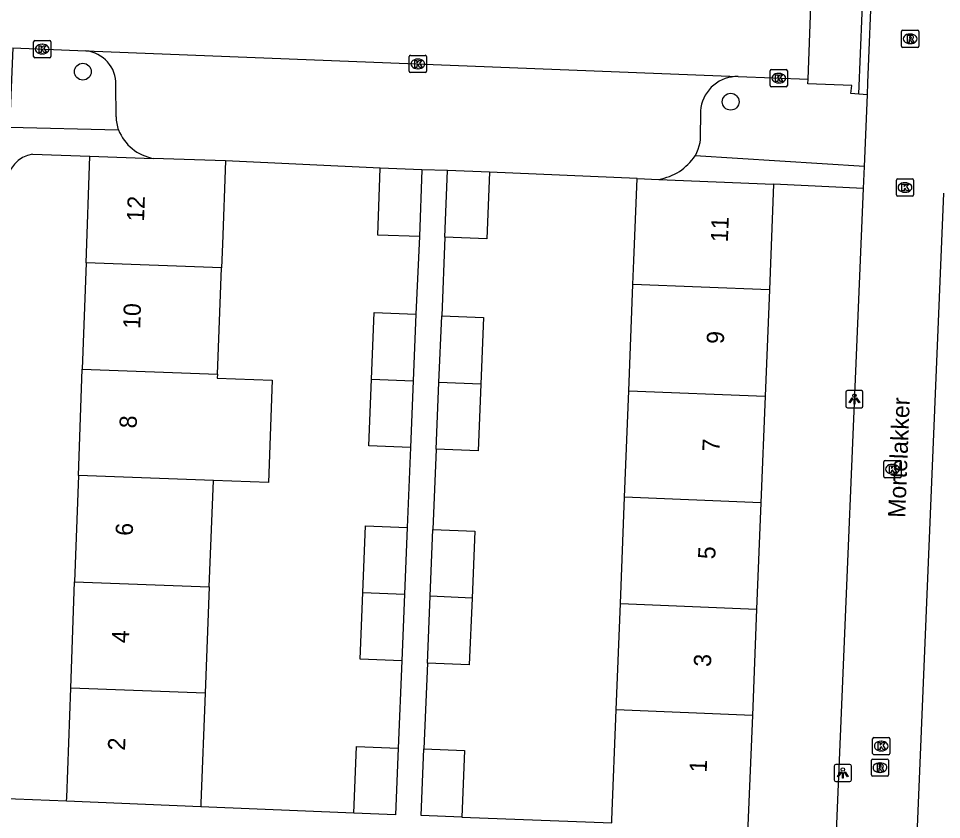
# Model space of a CAD drawing. Extents: x 161355 to 162026, y 386504 to 387459.
# Drawn here: x 161623.1 to 161676.7, y 386682.8 to 386729.4 of the extents above; entities that cross this region are included whole.
import ezdxf

# ---------------------------------------------------------------- set-up
doc = ezdxf.new("R2010")
doc.units = 0
for name, color, linetype in [('IMGEO_Boom', 7, 'Continuous'), ('IMGEO_Kolk', 7, 'Continuous'), ('IMGEO_Lichtpunt', 7, 'Continuous'), ('IMGEO_Openbare_ruimte_label', 7, 'Continuous'), ('IMGEO_Pand', 7, 'Continuous'), ('IMGEO_Pand_nummerreeks', 7, 'Continuous'), ('IMGEO_Parkeervlak_open', 7, 'Continuous'), ('IMGEO_Rijbaan_lokaal_open', 7, 'Continuous'), ('IMGEO_Rioolput', 7, 'Continuous'), ('IMGEO_Voetpad_open', 7, 'Continuous')]:
    doc.layers.add(name, color=color, linetype=linetype)

msp = doc.modelspace()

# ---------------------------------------------------------------- linework, layer by layer
at = {"layer": 'IMGEO_Boom'}
for centre in [(161626.866, 386726.264), (161664.481, 386724.517)]:
    msp.add_circle(centre, 0.489, dxfattribs=at)
at = {"layer": 'IMGEO_Kolk'}
for p, q in [((161624.007, 386727.146), (161624.007, 386727.998)), ((161624.082, 386728.072), (161624.934, 386728.072)), ((161624.495, 386727.852), (161624.52, 386727.852)), ((161625.008, 386727.998), (161625.008, 386727.146)), ((161624.518, 386727.292), (161624.493, 386727.292)), ((161624.934, 386727.072), (161624.082, 386727.072)), ((161645.819, 386726.286), (161645.819, 386727.138)), ((161645.894, 386727.212), (161646.746, 386727.212)), ((161646.307, 386726.992), (161646.332, 386726.992)), ((161646.82, 386727.138), (161646.82, 386726.286)), ((161646.746, 386726.212), (161645.894, 386726.212)), ((161646.33, 386726.432), (161646.305, 386726.432)), ((161666.772, 386725.459), (161666.772, 386726.311)), ((161666.847, 386726.385), (161667.699, 386726.385)), ((161667.773, 386726.311), (161667.773, 386725.459)), ((161667.26, 386726.165), (161667.285, 386726.165)), ((161667.699, 386725.385), (161666.847, 386725.385)), ((161667.283, 386725.605), (161667.258, 386725.605)), ((161674.102, 386719.107), (161674.102, 386719.959)), ((161674.177, 386720.033), (161675.029, 386720.033)), ((161674.59, 386719.813), (161674.615, 386719.813)), ((161675.103, 386719.959), (161675.103, 386719.107)), ((161674.613, 386719.253), (161674.588, 386719.253)), ((161675.029, 386719.033), (161674.177, 386719.033)), ((161673.452, 386703.666), (161674.304, 386703.666)), ((161673.377, 386702.74), (161673.377, 386703.592)), ((161673.865, 386703.446), (161673.89, 386703.446)), ((161674.378, 386703.592), (161674.378, 386702.74)), ((161674.304, 386702.666), (161673.452, 386702.666)), ((161673.888, 386702.886), (161673.863, 386702.886)), ((161672.723, 386686.65), (161672.723, 386687.502)), ((161672.798, 386687.576), (161673.65, 386687.576)), ((161673.211, 386687.356), (161673.236, 386687.356)), ((161673.724, 386687.502), (161673.724, 386686.65)), ((161673.65, 386686.576), (161672.798, 386686.576)), ((161673.234, 386686.796), (161673.209, 386686.796))]:
    msp.add_line(p, q, dxfattribs=at)
for points in [[(161624.007, 386727.146), (161624.007, 386727.998)], [(161624.082, 386728.072), (161624.934, 386728.072)], [(161625.008, 386727.998), (161625.008, 386727.146)], [(161624.328, 386727.772), (161624.451, 386727.772), (161624.451, 386727.621), (161624.581, 386727.772), (161624.745, 386727.772), (161624.599, 386727.621), (161624.752, 386727.372), (161624.6, 386727.372), (161624.515, 386727.536), (161624.451, 386727.469), (161624.451, 386727.372), (161624.328, 386727.372), (161624.328, 386727.772)], [(161624.934, 386727.072), (161624.082, 386727.072)], [(161645.819, 386726.286), (161645.819, 386727.138)], [(161645.894, 386727.212), (161646.746, 386727.212)], [(161646.14, 386726.912), (161646.263, 386726.912), (161646.263, 386726.761), (161646.393, 386726.912), (161646.557, 386726.912), (161646.411, 386726.761), (161646.564, 386726.512), (161646.412, 386726.512), (161646.327, 386726.676), (161646.263, 386726.609), (161646.263, 386726.512), (161646.14, 386726.512), (161646.14, 386726.912)], [(161646.82, 386727.138), (161646.82, 386726.286)], [(161646.746, 386726.212), (161645.894, 386726.212)], [(161666.772, 386725.459), (161666.772, 386726.311)], [(161666.847, 386726.385), (161667.699, 386726.385)], [(161667.773, 386726.311), (161667.773, 386725.459)], [(161667.093, 386726.085), (161667.216, 386726.085), (161667.216, 386725.934), (161667.346, 386726.085), (161667.51, 386726.085), (161667.364, 386725.934), (161667.517, 386725.685), (161667.365, 386725.685), (161667.28, 386725.849), (161667.216, 386725.782), (161667.216, 386725.685), (161667.093, 386725.685), (161667.093, 386726.085)], [(161667.699, 386725.385), (161666.847, 386725.385)], [(161674.102, 386719.107), (161674.102, 386719.959)], [(161674.177, 386720.033), (161675.029, 386720.033)], [(161675.103, 386719.959), (161675.103, 386719.107)], [(161674.423, 386719.733), (161674.546, 386719.733), (161674.546, 386719.582), (161674.676, 386719.733), (161674.84, 386719.733), (161674.694, 386719.582), (161674.847, 386719.333), (161674.695, 386719.333), (161674.61, 386719.497), (161674.546, 386719.43), (161674.546, 386719.333), (161674.423, 386719.333), (161674.423, 386719.733)], [(161675.029, 386719.033), (161674.177, 386719.033)], [(161673.452, 386703.666), (161674.304, 386703.666)], [(161673.377, 386702.74), (161673.377, 386703.592)], [(161673.698, 386703.366), (161673.821, 386703.366), (161673.821, 386703.215), (161673.951, 386703.366), (161674.115, 386703.366), (161673.969, 386703.215), (161674.122, 386702.966), (161673.97, 386702.966), (161673.885, 386703.13), (161673.821, 386703.063), (161673.821, 386702.966), (161673.698, 386702.966), (161673.698, 386703.366)], [(161674.378, 386703.592), (161674.378, 386702.74)], [(161674.304, 386702.666), (161673.452, 386702.666)], [(161672.723, 386686.65), (161672.723, 386687.502)], [(161672.798, 386687.576), (161673.65, 386687.576)], [(161673.044, 386687.276), (161673.167, 386687.276), (161673.167, 386687.125), (161673.297, 386687.276), (161673.461, 386687.276), (161673.315, 386687.125), (161673.468, 386686.876), (161673.316, 386686.876), (161673.231, 386687.04), (161673.167, 386686.973), (161673.167, 386686.876), (161673.044, 386686.876), (161673.044, 386687.276)], [(161673.724, 386687.502), (161673.724, 386686.65)], [(161673.65, 386686.576), (161672.798, 386686.576)]]:
    msp.add_lwpolyline(points, dxfattribs=at)
for centre, start, end in [((161624.084, 386727.996), 91.552, 178.448), ((161624.084, 386727.996), 91.552, 178.448), ((161624.932, 386727.996), 1.552, 88.448), ((161624.932, 386727.996), 1.552, 88.448), ((161624.084, 386727.148), 181.552, 268.448), ((161624.084, 386727.148), 181.552, 268.448), ((161624.932, 386727.148), 271.552, 358.448), ((161624.932, 386727.148), 271.552, 358.448), ((161645.896, 386727.136), 91.552, 178.448), ((161645.896, 386727.136), 91.552, 178.448), ((161646.744, 386727.136), 1.552, 88.448), ((161646.744, 386727.136), 1.552, 88.448), ((161645.896, 386726.288), 181.552, 268.448), ((161645.896, 386726.288), 181.552, 268.448), ((161646.744, 386726.288), 271.552, 358.448), ((161646.744, 386726.288), 271.552, 358.448), ((161666.849, 386726.309), 91.552, 178.448), ((161666.849, 386726.309), 91.552, 178.448), ((161667.697, 386726.309), 1.552, 88.448), ((161667.697, 386726.309), 1.552, 88.448), ((161666.849, 386725.461), 181.552, 268.448), ((161666.849, 386725.461), 181.552, 268.448), ((161667.697, 386725.461), 271.552, 358.448), ((161667.697, 386725.461), 271.552, 358.448), ((161674.179, 386719.957), 91.552, 178.448), ((161674.179, 386719.957), 91.552, 178.448), ((161675.027, 386719.957), 1.552, 88.448), ((161675.027, 386719.957), 1.552, 88.448), ((161674.179, 386719.109), 181.552, 268.448), ((161674.179, 386719.109), 181.552, 268.448), ((161675.027, 386719.109), 271.552, 358.448), ((161675.027, 386719.109), 271.552, 358.448), ((161673.454, 386703.59), 91.552, 178.448), ((161673.454, 386703.59), 91.552, 178.448), ((161674.302, 386703.59), 1.552, 88.448), ((161674.302, 386703.59), 1.552, 88.448), ((161673.454, 386702.742), 181.552, 268.448), ((161673.454, 386702.742), 181.552, 268.448), ((161674.302, 386702.742), 271.552, 358.448), ((161674.302, 386702.742), 271.552, 358.448), ((161672.8, 386687.5), 91.552, 178.448), ((161672.8, 386687.5), 91.552, 178.448), ((161673.648, 386687.5), 1.552, 88.448), ((161673.648, 386687.5), 1.552, 88.448), ((161672.8, 386686.652), 181.552, 268.448), ((161672.8, 386686.652), 181.552, 268.448), ((161673.648, 386686.652), 271.552, 358.448), ((161673.648, 386686.652), 271.552, 358.448)]:
    msp.add_arc(centre, 0.0765, start, end, dxfattribs=at)
for centre, major_axis, ratio, start_param, end_param in [((161624.494, 386727.572), (-0.387, 0.002), 0.722429, 4.712389, 7.853982), ((161624.519, 386727.572), (-0.39, 0.002), 0.717154, 1.570796, 4.712389), ((161646.306, 386726.712), (-0.387, 0.002), 0.722429, 4.712389, 7.853982), ((161646.331, 386726.712), (-0.39, 0.002), 0.717154, 1.570796, 4.712389), ((161667.259, 386725.885), (-0.387, 0.002), 0.722429, 4.712389, 7.853982), ((161667.284, 386725.885), (-0.39, 0.002), 0.717154, 1.570796, 4.712389), ((161674.589, 386719.533), (-0.387, 0.002), 0.722429, 4.712389, 7.853982), ((161674.614, 386719.533), (-0.39, 0.002), 0.717154, 1.570796, 4.712389), ((161673.864, 386703.166), (-0.387, 0.002), 0.722429, 4.712389, 7.853982), ((161673.889, 386703.166), (-0.39, 0.002), 0.717154, 1.570796, 4.712389), ((161673.21, 386687.076), (-0.387, 0.002), 0.722429, 4.712389, 7.853982), ((161673.235, 386687.076), (-0.39, 0.002), 0.717154, 1.570796, 4.712389)]:
    msp.add_ellipse(centre, major_axis=major_axis, ratio=ratio, start_param=start_param, end_param=end_param, dxfattribs=at)
at = {"layer": 'IMGEO_Lichtpunt'}
for p, q in [((161671.167, 386707.641), (161671.167, 386706.834)), ((161671.167, 386707.641), (161671.167, 386706.834)), ((161672.069, 386707.736), (161671.261, 386707.736)), ((161672.069, 386707.736), (161671.261, 386707.736)), ((161672.163, 386706.834), (161672.163, 386707.641)), ((161672.163, 386706.834), (161672.163, 386707.641)), ((161671.261, 386706.74), (161672.069, 386706.74)), ((161671.261, 386706.74), (161672.069, 386706.74)), ((161671.399, 386686.012), (161670.591, 386686.012)), ((161671.399, 386686.012), (161670.591, 386686.012)), ((161670.497, 386685.917), (161670.497, 386685.11)), ((161670.497, 386685.917), (161670.497, 386685.11)), ((161671.493, 386685.11), (161671.493, 386685.917)), ((161671.493, 386685.11), (161671.493, 386685.917)), ((161670.591, 386685.016), (161671.399, 386685.016)), ((161670.591, 386685.016), (161671.399, 386685.016))]:
    msp.add_line(p, q, dxfattribs=at)
for points in [[(161671.541, 386707.305), (161671.58, 386707.277), (161671.392, 386707.015), (161671.354, 386707.042), (161671.541, 386707.305)], [(161671.643, 386707.257), (161671.69, 386707.257), (161671.69, 386706.935), (161671.643, 386706.935), (161671.643, 386707.257)], [(161671.753, 386707.277), (161671.791, 386707.304), (161671.978, 386707.042), (161671.939, 386707.014), (161671.753, 386707.277)], [(161670.871, 386685.581), (161670.91, 386685.553), (161670.722, 386685.291), (161670.684, 386685.318), (161670.871, 386685.581)], [(161670.973, 386685.533), (161671.02, 386685.533), (161671.02, 386685.211), (161670.973, 386685.211), (161670.973, 386685.533)], [(161671.083, 386685.553), (161671.121, 386685.58), (161671.308, 386685.318), (161671.269, 386685.29), (161671.083, 386685.553)]]:
    msp.add_lwpolyline(points, dxfattribs=at)
for centre in [(161671.666, 386707.439), (161670.996, 386685.715)]:
    msp.add_circle(centre, 0.0994, dxfattribs=at)
for centre, start, end in [((161671.261, 386707.641), 90, 180), ((161671.261, 386707.641), 90, 180), ((161672.069, 386707.641), 0, 90), ((161672.069, 386707.641), 0, 90), ((161671.261, 386706.834), 180, 270), ((161671.261, 386706.834), 180, 270), ((161672.069, 386706.834), 270, 0), ((161672.069, 386706.834), 270, 360), ((161670.591, 386685.917), 90, 180), ((161670.591, 386685.917), 90, 180), ((161671.399, 386685.917), 0, 90), ((161671.399, 386685.917), 0, 90), ((161670.591, 386685.11), 180, 270), ((161670.591, 386685.11), 180, 270), ((161671.399, 386685.11), 270, 0), ((161671.399, 386685.11), 270, 360)]:
    msp.add_arc(centre, 0.0946, start, end, dxfattribs=at)
at = {"layer": 'IMGEO_Pand'}
for points in [[(161627.05, 386715.155), (161627.272, 386721.352)], [(161627.272, 386721.352), (161630.958, 386721.225)], [(161635.144, 386721.081), (161630.958, 386721.225)], [(161635.144, 386721.081), (161634.973, 386716.244), (161634.92, 386714.872)], [(161646.416, 386716.687), (161643.987, 386716.772), (161644.122, 386720.65)], [(161646.551, 386720.565), (161644.122, 386720.65)], [(161646.551, 386720.565), (161646.416, 386716.687)], [(161647.888, 386716.644), (161648.047, 386720.523)], [(161650.475, 386720.422), (161650.316, 386716.545), (161647.888, 386716.644)], [(161650.475, 386720.422), (161648.047, 386720.523)], [(161658.808, 386713.895), (161658.863, 386715.297), (161659.045, 386720.06)], [(161659.045, 386720.06), (161660.306, 386720.007)], [(161660.306, 386720.007), (161666.975, 386719.725)], [(161666.975, 386719.725), (161666.729, 386713.578)], [(161627.05, 386715.155), (161626.828, 386708.975)], [(161634.92, 386714.872), (161627.05, 386715.155)], [(161634.683, 386708.693), (161634.92, 386714.872)], [(161658.564, 386707.716), (161658.808, 386713.895)], [(161666.729, 386713.578), (161658.808, 386713.895)], [(161666.729, 386713.578), (161666.482, 386707.399)], [(161643.624, 386708.397), (161643.782, 386712.274), (161646.21, 386712.175)], [(161646.21, 386712.175), (161646.052, 386708.298)], [(161647.543, 386708.205), (161647.702, 386712.082)], [(161647.702, 386712.082), (161650.13, 386711.983), (161649.971, 386708.106)], [(161626.606, 386702.795), (161626.828, 386708.975)], [(161626.828, 386708.975), (161634.683, 386708.693)], [(161634.683, 386708.693), (161634.674, 386708.457), (161637.866, 386708.334), (161637.639, 386702.398), (161634.446, 386702.513)], [(161645.894, 386704.421), (161643.466, 386704.52), (161643.624, 386708.397)], [(161643.624, 386708.397), (161646.052, 386708.298)], [(161646.052, 386708.298), (161645.894, 386704.421)], [(161647.385, 386704.328), (161647.543, 386708.205)], [(161649.971, 386708.106), (161649.813, 386704.229), (161647.385, 386704.328)], [(161649.971, 386708.106), (161647.543, 386708.205)], [(161658.32, 386701.537), (161658.564, 386707.716)], [(161658.564, 386707.716), (161666.482, 386707.399)], [(161666.482, 386707.399), (161666.235, 386701.22)], [(161626.606, 386702.795), (161626.384, 386696.614)], [(161634.446, 386702.513), (161626.606, 386702.795)], [(161634.208, 386696.333), (161634.446, 386702.513)], [(161658.076, 386695.357), (161658.32, 386701.537)], [(161666.235, 386701.22), (161658.32, 386701.537)], [(161666.235, 386701.22), (161665.989, 386695.04)], [(161643.119, 386695.998), (161643.277, 386699.874), (161645.705, 386699.776)], [(161645.705, 386699.776), (161645.547, 386695.899)], [(161647.036, 386695.78), (161647.194, 386699.656)], [(161647.194, 386699.656), (161649.622, 386699.557), (161649.463, 386695.68)], [(161626.162, 386690.434), (161626.384, 386696.614)], [(161626.384, 386696.614), (161634.208, 386696.333)], [(161634.208, 386696.333), (161633.971, 386690.153)], [(161645.39, 386692.022), (161642.962, 386692.121), (161643.119, 386695.998)], [(161643.119, 386695.998), (161645.547, 386695.899)], [(161645.547, 386695.899), (161645.39, 386692.022)], [(161646.877, 386691.903), (161647.036, 386695.78)], [(161649.463, 386695.68), (161649.305, 386691.804), (161646.877, 386691.903)], [(161649.463, 386695.68), (161647.036, 386695.78)], [(161657.832, 386689.178), (161658.076, 386695.357)], [(161658.076, 386695.357), (161665.989, 386695.04)], [(161665.989, 386695.04), (161665.742, 386688.861)], [(161625.926, 386683.868), (161625.934, 386684.081), (161626.162, 386690.434)], [(161633.971, 386690.153), (161626.162, 386690.434)], [(161633.971, 386690.153), (161633.725, 386683.757), (161633.717, 386683.547)], [(161657.573, 386682.613), (161657.58, 386682.8), (161657.832, 386689.178)], [(161665.742, 386688.861), (161657.832, 386689.178)], [(161665.742, 386688.861), (161665.486, 386682.462), (161665.48, 386682.303)], [(161642.598, 386683.18), (161642.756, 386687.057), (161645.184, 386686.958)], [(161645.184, 386686.958), (161645.026, 386683.081), (161642.598, 386683.18)], [(161648.868, 386682.954), (161646.515, 386683.046), (161646.673, 386686.923)], [(161646.673, 386686.923), (161649.026, 386686.82), (161648.868, 386682.954)], [(161633.717, 386683.547), (161625.926, 386683.868)]]:
    msp.add_lwpolyline(points, dxfattribs=at)
at = {"layer": 'IMGEO_Parkeervlak_open'}
for points in [[(161664.918, 386725.979), (161664.726, 386725.975), (161664.535, 386725.953), (161664.347, 386725.915), (161664.163, 386725.86), (161663.984, 386725.789), (161663.813, 386725.702), (161663.65, 386725.6), (161663.497, 386725.484), (161663.355, 386725.355), (161663.225, 386725.214), (161663.108, 386725.062), (161663.005, 386724.899), (161662.917, 386724.729), (161662.845, 386724.551), (161662.789, 386724.367), (161662.749, 386724.179), (161662.727, 386723.988), (161662.721, 386723.847), (161662.71, 386722.474), (161662.704, 386722.333), (161662.681, 386722.133), (161662.64, 386721.936), (161662.581, 386721.743), (161662.506, 386721.556), (161662.414, 386721.377)], [(161628.8, 386723.638), (161628.788, 386725.495)], [(161644.122, 386720.65), (161635.144, 386721.081)], [(161659.045, 386720.06), (161650.475, 386720.422)]]:
    msp.add_lwpolyline(points, dxfattribs=at)
for centre, radius, start, end in [((161626.846, 386725.541), 1.943, 358.6417, 84.1673), ((161631.036, 386723.641), 2.236, 180.0895, 199.935)]:
    msp.add_arc(centre, radius, start, end, dxfattribs=at)
at = {"layer": 'IMGEO_Rijbaan_lokaal_open'}
for points in [[(161668.978, 386725.819), (161669.197, 386731.672)], [(161671.927, 386724.955), (161672.205, 386732.064)], [(161672.419, 386724.921), (161672.447, 386725.608), (161672.693, 386731.752), (161672.705, 386732.061)], [(161622.797, 386727.641), (161627.043, 386727.474)], [(161627.043, 386727.474), (161664.918, 386725.979)], [(161664.918, 386725.979), (161668.978, 386725.819)], [(161671.927, 386724.955), (161671.459, 386724.986), (161671.513, 386725.456), (161668.962, 386725.564), (161668.978, 386725.819)], [(161672.252, 386720.745), (161672.419, 386724.921)], [(161672.201, 386719.472), (161672.252, 386720.745)], [(161670.634, 386682.096), (161672.201, 386719.472)], [(161676.837, 386719.2), (161675.298, 386681.892)]]:
    msp.add_lwpolyline(points, dxfattribs=at)
at = {"layer": 'IMGEO_Rioolput'}
for p, q in [((161674.399, 386727.745), (161674.399, 386728.597)), ((161674.474, 386728.671), (161675.326, 386728.671)), ((161674.887, 386728.451), (161674.912, 386728.451)), ((161675.4, 386728.597), (161675.4, 386727.745)), ((161674.91, 386727.891), (161674.885, 386727.891)), ((161675.326, 386727.671), (161674.474, 386727.671)), ((161672.65, 386685.397), (161672.65, 386686.249)), ((161672.725, 386686.323), (161673.577, 386686.323)), ((161673.138, 386686.103), (161673.163, 386686.103)), ((161673.651, 386686.249), (161673.651, 386685.397)), ((161673.161, 386685.543), (161673.136, 386685.543)), ((161673.577, 386685.323), (161672.725, 386685.323))]:
    msp.add_line(p, q, dxfattribs=at)
for points in [[(161674.399, 386727.745), (161674.399, 386728.597)], [(161674.474, 386728.671), (161675.326, 386728.671)], [(161674.988, 386728.369), (161674.736, 386728.371), (161674.736, 386727.971)], [(161675.4, 386728.597), (161675.4, 386727.745)], [(161674.736, 386727.971), (161674.86, 386727.971), (161674.86, 386728.133), (161674.871, 386728.133)], [(161674.914, 386728.29), (161674.86, 386728.29), (161674.86, 386728.209)], [(161674.86, 386728.209), (161674.912, 386728.209)], [(161674.918, 386728.104), (161674.989, 386727.971), (161675.129, 386727.971), (161675.064, 386728.097)], [(161675.326, 386727.671), (161674.474, 386727.671)], [(161672.65, 386685.397), (161672.65, 386686.249)], [(161672.725, 386686.323), (161673.577, 386686.323)], [(161673.239, 386686.021), (161672.987, 386686.023), (161672.987, 386685.623)], [(161673.651, 386686.249), (161673.651, 386685.397)], [(161672.987, 386685.623), (161673.111, 386685.623), (161673.111, 386685.785), (161673.122, 386685.785)], [(161673.165, 386685.942), (161673.111, 386685.942), (161673.111, 386685.861)], [(161673.111, 386685.861), (161673.163, 386685.861)], [(161673.169, 386685.756), (161673.24, 386685.623), (161673.38, 386685.623), (161673.315, 386685.749)], [(161673.577, 386685.323), (161672.725, 386685.323)]]:
    msp.add_lwpolyline(points, dxfattribs=at)
for centre, radius, start, end in [((161674.476, 386728.595), 0.0765, 91.552, 178.448), ((161674.476, 386728.595), 0.0765, 91.552, 178.448), ((161674.987, 386728.259), 0.109, 350.3612, 89.416), ((161675.324, 386728.595), 0.0765, 1.552, 88.448), ((161675.324, 386728.595), 0.0765, 1.552, 88.448), ((161674.87, 386728.08), 0.0533, 26.0293, 88.6989), ((161674.896, 386728.398), 0.19, 274.7715, 282.9687), ((161674.92, 386728.194), 0.0964, 77.0061, 93.1865), ((161674.934, 386728.251), 0.0378, 276.6634, 79.6772), ((161674.985, 386728.259), 0.112, 277.5842, 350.9817), ((161674.969, 386728.044), 0.108, 29.5134, 73.7905), ((161674.476, 386727.747), 0.0765, 181.552, 268.448), ((161674.476, 386727.747), 0.0765, 181.552, 268.448), ((161675.324, 386727.747), 0.0765, 271.552, 358.448), ((161675.324, 386727.747), 0.0765, 271.552, 358.448), ((161672.727, 386686.247), 0.0765, 91.552, 178.448), ((161672.727, 386686.247), 0.0765, 91.552, 178.448), ((161673.238, 386685.911), 0.109, 350.3612, 89.416), ((161673.575, 386686.247), 0.0765, 1.552, 88.448), ((161673.575, 386686.247), 0.0765, 1.552, 88.448), ((161673.121, 386685.732), 0.0533, 26.0293, 88.6989), ((161673.147, 386686.05), 0.19, 274.7715, 282.9687), ((161673.171, 386685.846), 0.0964, 77.0061, 93.1865), ((161673.185, 386685.903), 0.0378, 276.6634, 79.6772), ((161673.236, 386685.911), 0.112, 277.5842, 350.9817), ((161673.22, 386685.696), 0.108, 29.5134, 73.7905), ((161672.727, 386685.399), 0.0765, 181.552, 268.448), ((161672.727, 386685.399), 0.0765, 181.552, 268.448), ((161673.575, 386685.399), 0.0765, 271.552, 358.448), ((161673.575, 386685.399), 0.0765, 271.552, 358.448)]:
    msp.add_arc(centre, radius, start, end, dxfattribs=at)
for centre, major_axis, ratio, start_param, end_param in [((161674.886, 386728.171), (-0.387, 0.002), 0.722429, 4.712389, 7.853982), ((161674.911, 386728.171), (-0.39, 0.002), 0.717154, 1.570796, 4.712389), ((161673.137, 386685.823), (-0.387, 0.002), 0.722429, 4.712389, 7.853982), ((161673.162, 386685.823), (-0.39, 0.002), 0.717154, 1.570796, 4.712389)]:
    msp.add_ellipse(centre, major_axis=major_axis, ratio=ratio, start_param=start_param, end_param=end_param, dxfattribs=at)
at = {"layer": 'IMGEO_Voetpad_open'}
for points in [[(161622.797, 386727.641), (161622.601, 386723.035), (161628.934, 386722.879)], [(161672.419, 386724.921), (161671.927, 386724.955)], [(161623.948, 386721.467), (161627.272, 386721.352)], [(161672.252, 386720.745), (161662.414, 386721.377)], [(161648.047, 386720.523), (161646.551, 386720.565)], [(161672.201, 386719.472), (161666.975, 386719.725)], [(161646.416, 386716.687), (161646.21, 386712.175)], [(161647.888, 386716.644), (161647.702, 386712.082)], [(161645.894, 386704.421), (161645.705, 386699.776)], [(161647.385, 386704.328), (161647.194, 386699.656)], [(161645.39, 386692.022), (161645.184, 386686.958)], [(161646.877, 386691.903), (161646.673, 386686.923)], [(161625.926, 386683.868), (161620.97, 386684.073)], [(161642.598, 386683.18), (161633.717, 386683.547)], [(161648.868, 386682.954), (161657.573, 386682.613)]]:
    msp.add_lwpolyline(points, dxfattribs=at)
for centre, radius, start, end in [((161631.438, 386723.878), 2.696, 201.7513, 259.7377), ((161624.231, 386719.71), 1.78, 99.1637, 177.5396), ((161659.794, 386723.102), 3.137, 279.3954, 326.6447)]:
    msp.add_arc(centre, radius, start, end, dxfattribs=at)

# ---------------------------------------------------------------- texts
at = {"layer": 'IMGEO_Openbare_ruimte_label'}
msp.add_text('Mortelakker', height=1, rotation=87.7644, dxfattribs=at).set_placement((161674.614, 386700.328))
at = {"layer": 'IMGEO_Pand_nummerreeks'}
for s, rotation, p in [('12', 87.9433, (161630.417, 386717.537)), ('11', 87.7141, (161664.316, 386716.334)), ('10', 87.9436, (161630.194, 386711.305)), ('9', 87.7121, (161664.082, 386710.428)), ('8', 87.9433, (161629.987, 386705.527)), ('7', 87.7121, (161663.832, 386704.174)), ('6', 87.9436, (161629.761, 386699.284)), ('5', 87.7121, (161663.582, 386697.921)), ('4', 87.9436, (161629.537, 386693.046)), ('3', 87.7121, (161663.332, 386691.668)), ('2', 87.9433, (161629.314, 386686.805)), ('1', 87.7141, (161663.086, 386685.528))]:
    msp.add_text(s, height=1, rotation=rotation, dxfattribs=at).set_placement(p)

doc.saveas('drawing.dxf')
